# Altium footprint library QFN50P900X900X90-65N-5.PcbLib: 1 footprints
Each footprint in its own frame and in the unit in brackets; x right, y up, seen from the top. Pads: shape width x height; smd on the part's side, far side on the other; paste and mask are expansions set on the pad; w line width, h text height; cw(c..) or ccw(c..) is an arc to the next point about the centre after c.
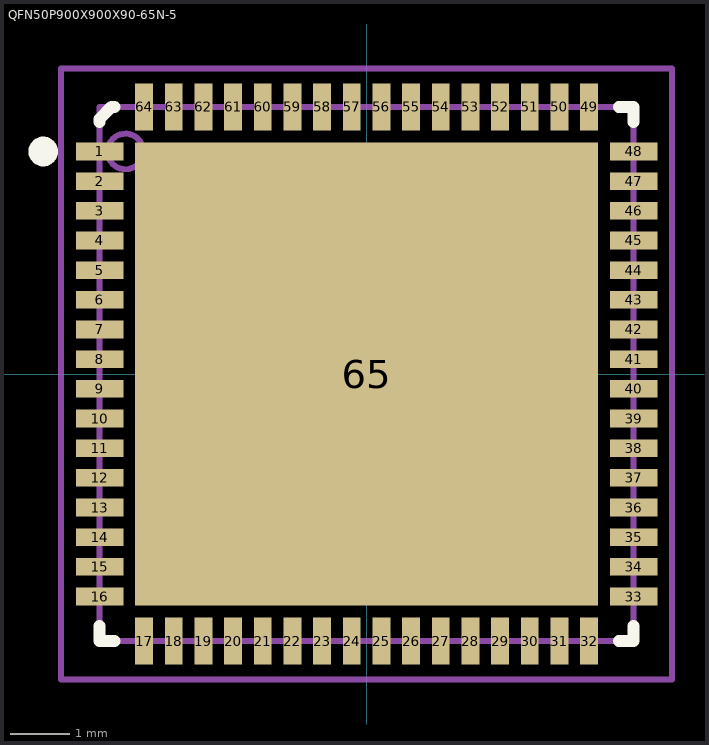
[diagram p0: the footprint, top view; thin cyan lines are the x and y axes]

## QFN50P900X900X90-65N-5 [mm] "QFN,0.50mm pitch,square;64 pin,9.00mm L X 9.00mm W X 0.90mm H body (w/thermal tab)"
height 0.9
pads (65):
  rect 0.8x0.3 smd paste+0 mask+0: 1(-4.5,3.75) 2(-4.5,3.25) 3(-4.5,2.75) 4(-4.5,2.25) 5(-4.5,1.75) 6(-4.5,1.25) 7(-4.5,0.75) 8(-4.5,0.25) 9(-4.5,-0.25) 10(-4.5,-0.75) 11(-4.5,-1.25) 12(-4.5,-1.75) 13(-4.5,-2.25) 14(-4.5,-2.75) 15(-4.5,-3.25) 16(-4.5,-3.75) 33(4.5,-3.75) 34(4.5,-3.25) 35(4.5,-2.75) 36(4.5,-2.25) 37(4.5,-1.75) 38(4.5,-1.25) 39(4.5,-0.75) 40(4.5,-0.25) 41(4.5,0.25) 42(4.5,0.75) 43(4.5,1.25) 44(4.5,1.75) 45(4.5,2.25) 46(4.5,2.75) 47(4.5,3.25) 48(4.5,3.75)
  rect 0.3x0.8 smd paste+0 mask+0: 17(-3.75,-4.5) 18(-3.25,-4.5) 19(-2.75,-4.5) 20(-2.25,-4.5) 21(-1.75,-4.5) 22(-1.25,-4.5) 23(-0.75,-4.5) 24(-0.25,-4.5) 25(0.25,-4.5) 26(0.75,-4.5) 27(1.25,-4.5) 28(1.75,-4.5) 29(2.25,-4.5) 30(2.75,-4.5) 31(3.25,-4.5) 32(3.75,-4.5) 49(3.75,4.5) 50(3.25,4.5) 51(2.75,4.5) 52(2.25,4.5) 53(1.75,4.5) 54(1.25,4.5) 55(0.75,4.5) 56(0.25,4.5) 57(-0.25,4.5) 58(-0.75,4.5) 59(-1.25,4.5) 60(-1.75,4.5) 61(-2.25,4.5) 62(-2.75,4.5) 63(-3.25,4.5) 64(-3.75,4.5)
  rect 7.8x7.8 smd paste+0 mask+0: 65(0,0)
Top Overlay:
  circle w0.25: c-5.45,3.75 r0.125
  lines w0.2: -4.5,-4.25 -4.5,-4.5 -4.25,-4.5 ; -4.5,4.25 -4.5,4.3 -4.3,4.5 -4.25,4.5 ; 4.25,-4.5 4.5,-4.5 4.5,-4.25 ; 4.25,4.5 4.5,4.5 4.5,4.25
M3 (ASY_Text_Top):
  text ".DESIGNATOR" at -3.643,-0.385 h1.2
M13 (CMP_Body_OTL_Top):
  circle w0.1: c-4.064,3.75 r0.3
  lines w0.1: -4.5,-4.5 -4.5,4.5 4.5,4.5 4.5,-4.5 -4.5,-4.5
M15 (CMP_Courtyard_Top):
  lines w0.1: -0.5,0 0.5,0 ; 0,-0.5 0,0.5 ; -5.15,-5.15 -5.15,5.15 5.15,5.15 5.15,-5.15 -5.15,-5.15
3D body "CY8C4147LQS-S285.STEP": height 0.9, standoff 0, extent -4.5,-4.5 4.5,4.5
